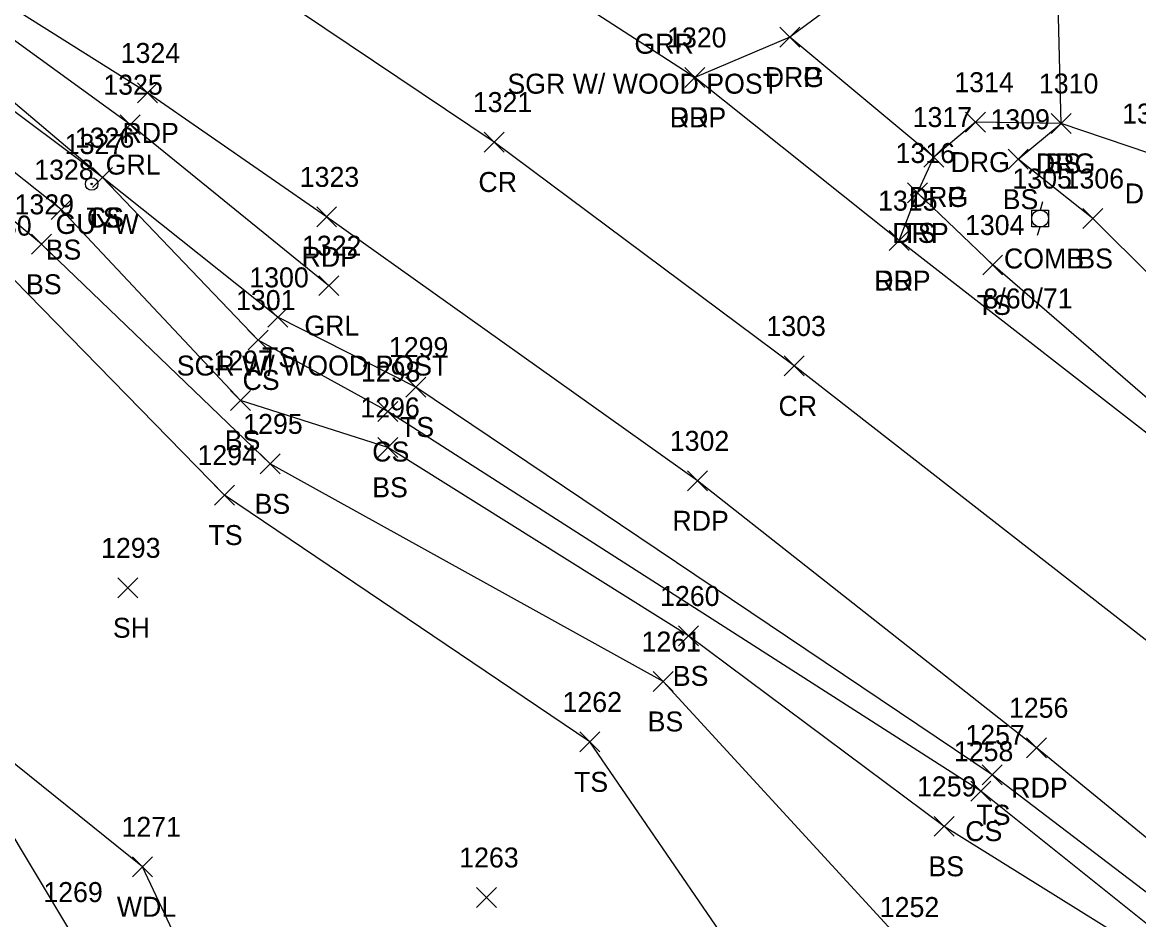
# Model space of a CAD drawing. Extents: x 1537342 to 1542195, y 163002 to 168596.
# Drawn here: x 1541827.1 to 1541938.8, y 163200.7 to 163290.5 of the extents above; entities that cross this region are included whole.
import ezdxf

# ---------------------------------------------------------------- set-up
doc = ezdxf.new("R2010")
doc.units = 0
for name, color, linetype in [('L_A', 7, 'Continuous'), ('L_I', 7, 'Continuous'), ('L_TIC', 7, 'Continuous'), ('LAWA', 7, 'Continuous'), ('LELB', 7, 'Continuous'), ('P_A', 7, 'Continuous'), ('P_I', 7, 'Continuous'), ('P_TIC', 7, 'Continuous'), ('PET', 7, 'Continuous'), ('PRC', 7, 'Continuous'), ('R_A', 7, 'Continuous'), ('R_C', 7, 'Continuous'), ('R_I', 7, 'Continuous'), ('R_TIC', 7, 'Continuous'), ('RDG', 7, 'Continuous'), ('RDP', 7, 'Continuous'), ('RGR', 7, 'Continuous'), ('U_A', 7, 'Continuous'), ('U_C', 7, 'Continuous'), ('U_I', 7, 'Continuous'), ('UP', 7, 'Continuous'), ('UPGW', 7, 'Continuous')]:
    doc.layers.add(name, color=color, linetype=linetype)

msp = doc.modelspace()

# ---------------------------------------------------------------- linework, layer by layer
at = {"layer": 'L_TIC'}
for points in [[(1541930.05, 163279.39), (1541932.05, 163281.39)], [(1541932.05, 163279.39), (1541930.05, 163281.39)], [(1541925.76, 163275.81), (1541927.76, 163277.81)], [(1541927.76, 163275.81), (1541925.76, 163277.81)], [(1541834.08, 163273.97), (1541836.08, 163275.97)], [(1541836.08, 163273.97), (1541834.08, 163275.97)], [(1541834.08, 163273.97), (1541836.08, 163275.97)], [(1541836.08, 163273.97), (1541834.08, 163275.97)], [(1541915.66, 163272.43), (1541917.66, 163274.43)], [(1541917.66, 163272.43), (1541915.66, 163274.43)], [(1541829.96, 163270.76), (1541831.96, 163272.76)], [(1541831.96, 163270.76), (1541829.96, 163272.76)], [(1541933.22, 163269.87), (1541935.22, 163271.87)], [(1541935.22, 163269.87), (1541933.22, 163271.87)], [(1541827.99, 163267.29), (1541829.99, 163269.29)], [(1541829.99, 163267.29), (1541827.99, 163269.29)], [(1541923.2, 163265.22), (1541925.2, 163267.22)], [(1541925.2, 163265.22), (1541923.2, 163267.22)], [(1541851.65, 163259.98), (1541853.65, 163261.98)], [(1541853.65, 163259.98), (1541851.65, 163261.98)], [(1541849.67, 163257.71), (1541851.67, 163259.71)], [(1541851.67, 163257.71), (1541849.67, 163259.71)], [(1541865.46, 163253), (1541867.46, 163255)], [(1541867.46, 163253), (1541865.46, 163255)], [(1541847.89, 163251.66), (1541849.89, 163253.66)], [(1541849.89, 163251.66), (1541847.89, 163253.66)], [(1541862.65, 163250.54), (1541864.65, 163252.54)], [(1541864.65, 163250.54), (1541862.65, 163252.54)], [(1541862.64, 163246.96), (1541864.64, 163248.96)], [(1541864.64, 163246.96), (1541862.64, 163248.96)], [(1541850.87, 163245.31), (1541852.87, 163247.31)], [(1541852.87, 163245.31), (1541850.87, 163247.31)], [(1541846.29, 163242.18), (1541848.29, 163244.18)], [(1541848.29, 163242.18), (1541846.29, 163244.18)], [(1541836.64, 163232.9), (1541838.64, 163234.9)], [(1541838.64, 163232.9), (1541836.64, 163234.9)], [(1541892.74, 163228.08), (1541894.74, 163230.08)], [(1541894.74, 163228.08), (1541892.74, 163230.08)], [(1541890.22, 163223.52), (1541892.22, 163225.52)], [(1541892.22, 163223.52), (1541890.22, 163225.52)], [(1541882.88, 163217.47), (1541884.88, 163219.47)], [(1541884.88, 163217.47), (1541882.88, 163219.47)], [(1541923.16, 163214.18), (1541925.16, 163216.18)], [(1541925.16, 163214.18), (1541923.16, 163216.18)], [(1541922.01, 163212.54), (1541924.01, 163214.54)], [(1541924.01, 163212.54), (1541922.01, 163214.54)], [(1541918.33, 163209.02), (1541920.33, 163211.02)], [(1541920.33, 163209.02), (1541918.33, 163211.02)], [(1541838.11, 163204.97), (1541840.11, 163206.97)], [(1541840.11, 163204.97), (1541838.11, 163206.97)], [(1541872.54, 163201.9), (1541874.54, 163203.9)], [(1541874.54, 163201.9), (1541872.54, 163203.9)]]:
    msp.add_lwpolyline(points, dxfattribs=at)
at = {"layer": 'LAWA'}
msp.add_lwpolyline([(1541844.86, 163168.93), (1541849.55, 163183.81), (1541839.11, 163205.97), (1541817.65, 163223.23), (1541815, 163239.81), (1541816.56, 163255.64), (1541792.4, 163274.28), (1541779.24, 163270.52), (1541762.88, 163259.76), (1541752.39, 163275.43), (1541738.68, 163268.21), (1541722.17, 163262.13), (1541701.08, 163257.12)], dxfattribs=at)
at = {"layer": 'LELB'}
for points in [[(1542002.44, 163218.44), (1541992.58, 163218.5), (1541981.66, 163227.08), (1541972.73, 163235.18), (1541952.24, 163252.94), (1541934.22, 163270.87), (1541926.76, 163276.81), (1541931.05, 163280.39), (1541930.67, 163296.4), (1541914.43, 163302.12), (1541899.5, 163302.03), (1541884.5, 163312), (1541872.6, 163319.6), (1541857.31, 163324.7)], [(1541981.52, 163166.61), (1541978.59, 163174.42), (1541956.98, 163190.15), (1541924.16, 163215.18), (1541866.46, 163254), (1541852.65, 163260.98), (1541835.08, 163274.97), (1541811.52, 163294.95), (1541800.6, 163304.36), (1541792.57, 163308.98)], [(1541955.89, 163187.24), (1541923.01, 163213.54), (1541863.65, 163251.54), (1541850.67, 163258.71), (1541835.08, 163274.97), (1541811.38, 163292.75), (1541797.03, 163303.08), (1541792.37, 163306.6)], [(1541982.35, 163154.54), (1541977.46, 163162.71), (1541976.49, 163171.88), (1541973.52, 163173.98), (1541972.19, 163175.21), (1541955.89, 163187.24), (1541919.33, 163210.02), (1541893.74, 163229.08), (1541863.64, 163247.96), (1541848.89, 163252.66), (1541830.96, 163271.76), (1541807.53, 163290.35), (1541793.3, 163299.34), (1541792.63, 163303.62)], [(1541920.52, 163124.04), (1541935.16, 163148.54), (1541933.92, 163173.02), (1541915.6, 163197.94), (1541891.22, 163224.52), (1541851.87, 163246.31), (1541828.99, 163268.29), (1541806.16, 163287.41), (1541789.02, 163298.58), (1541787.18, 163300.8)], [(1541912.53, 163131.42), (1541929, 163149.96), (1541922.93, 163163.15), (1541906.57, 163185.36), (1541883.88, 163218.47), (1541847.29, 163243.18), (1541824.83, 163266.16), (1541803.8, 163284.14), (1541786.25, 163296.89)], [(1541999.83, 163204.61), (1541992.06, 163211.09), (1541976.95, 163222.64), (1541968.56, 163229.41), (1541948.76, 163245.02), (1541924.2, 163266.22), (1541916.66, 163273.43)], [(1541844.86, 163168.93), (1541831.91, 163199.44), (1541817.65, 163223.23), (1541791.64, 163233.2), (1541773.3, 163225.27), (1541742.38, 163225.52), (1541715.33, 163231.42)]]:
    msp.add_lwpolyline(points, dxfattribs=at)
at = {"layer": 'P_TIC'}
for points in [[(1541893.39, 163284), (1541895.39, 163286)], [(1541895.39, 163284), (1541893.39, 163286)], [(1541838.6, 163282.45), (1541840.6, 163284.45)], [(1541840.6, 163282.45), (1541838.6, 163284.45)], [(1541873.29, 163277.53), (1541875.29, 163279.53)], [(1541875.29, 163277.53), (1541873.29, 163279.53)], [(1541856.53, 163270.04), (1541858.53, 163272.04)], [(1541858.53, 163270.04), (1541856.53, 163272.04)], [(1541913.85, 163267.66), (1541915.85, 163269.66)], [(1541915.85, 163267.66), (1541913.85, 163269.66)], [(1541903.32, 163255.11), (1541905.32, 163257.11)], [(1541905.32, 163255.11), (1541903.32, 163257.11)], [(1541893.65, 163243.61), (1541895.65, 163245.61)], [(1541895.65, 163243.61), (1541893.65, 163245.61)], [(1541927.58, 163216.89), (1541929.58, 163218.89)], [(1541929.58, 163216.89), (1541927.58, 163218.89)]]:
    msp.add_lwpolyline(points, dxfattribs=at)
at = {"layer": 'PET'}
for points in [[(1542165.56, 163030.05), (1542126.67, 163058.36), (1542096.32, 163082.47), (1542058.61, 163112.54), (1542052.02, 163117.84), (1542010.73, 163151.35), (1541978.73, 163177.48), (1541958.58, 163193.33), (1541928.58, 163217.89), (1541894.65, 163244.61), (1541857.53, 163271.04), (1541839.6, 163283.45), (1541795.58, 163311.16), (1541814.19, 163318.82), (1541832.22, 163326.69)], [(1542182.46, 163052.97), (1542144.74, 163083.14), (1542111.59, 163110.07), (1542069.86, 163143.45), (1542042.93, 163166.04), (1542014.58, 163189.13), (1541996.52, 163203.32), (1541975.27, 163220.84), (1541953.96, 163238.23), (1541914.85, 163268.66), (1541894.39, 163285), (1541874.19, 163298.08), (1541854.83, 163311.47), (1541832.22, 163326.69)]]:
    msp.add_lwpolyline(points, dxfattribs=at)
at = {"layer": 'PRC'}
msp.add_lwpolyline([(1542174.18, 163041.84), (1542135.38, 163070.51), (1542102.15, 163097.42), (1542058.02, 163132.98), (1542032.76, 163153.88), (1541982.81, 163194.28), (1541947.35, 163222.57), (1541904.32, 163256.11), (1541874.29, 163278.53), (1541825.99, 163311), (1541814.19, 163318.82)], dxfattribs=at)
at = {"layer": 'R_TIC'}
for points in [[(1541902.89, 163288.03), (1541904.89, 163290.03)], [(1541904.89, 163288.03), (1541902.89, 163290.03)], [(1541902.89, 163288.03), (1541904.89, 163290.03)], [(1541904.89, 163288.03), (1541902.89, 163290.03)], [(1541893.39, 163284), (1541895.39, 163286)], [(1541895.39, 163284), (1541893.39, 163286)], [(1541836.87, 163279.27), (1541838.87, 163281.27)], [(1541838.87, 163279.27), (1541836.87, 163281.27)], [(1541921.49, 163279.52), (1541923.49, 163281.52)], [(1541923.49, 163279.52), (1541921.49, 163281.52)], [(1541930.05, 163279.39), (1541932.05, 163281.39)], [(1541932.05, 163279.39), (1541930.05, 163281.39)], [(1541917.32, 163276.03), (1541919.32, 163278.03)], [(1541919.32, 163276.03), (1541917.32, 163278.03)], [(1541917.32, 163276.03), (1541919.32, 163278.03)], [(1541919.32, 163276.03), (1541917.32, 163278.03)], [(1541915.66, 163272.43), (1541917.66, 163274.43)], [(1541917.66, 163272.43), (1541915.66, 163274.43)], [(1541913.85, 163267.66), (1541915.85, 163269.66)], [(1541915.85, 163267.66), (1541913.85, 163269.66)], [(1541856.75, 163263.15), (1541858.75, 163265.15)], [(1541858.75, 163263.15), (1541856.75, 163265.15)]]:
    msp.add_lwpolyline(points, dxfattribs=at)
at = {"layer": 'RDG'}
for points in [[(1542017.62, 163206.92), (1542015.2, 163226.11), (1542009.88, 163243.69), (1541994.5, 163258.92), (1541988.52, 163265.14), (1541982.39, 163272.12), (1541977.91, 163278.25), (1541973.34, 163281.58), (1541963.15, 163285.49), (1541948.66, 163292.51), (1541930.67, 163296.4), (1541918.38, 163296.03), (1541913.61, 163296.24), (1541903.89, 163289.03)], [(1542002.85, 163214.55), (1542002.44, 163218.44), (1541997.04, 163236.79), (1541985.19, 163249.9), (1541958.7, 163267.58), (1541939.93, 163277.38), (1541931.05, 163280.39), (1541922.49, 163280.52), (1541918.32, 163277.03)]]:
    msp.add_lwpolyline(points, dxfattribs=at)
at = {"layer": 'RDP'}
msp.add_lwpolyline([(1541914.85, 163268.66), (1541916.66, 163273.43), (1541918.32, 163277.03), (1541903.89, 163289.03), (1541894.39, 163285)], dxfattribs=at)
at = {"layer": 'RGR'}
msp.add_lwpolyline([(1541857.75, 163264.15), (1541837.87, 163280.27), (1541804.45, 163304.56), (1541795.02, 163310.6)], dxfattribs=at)
at = {"layer": 'UP'}
for p, q in [((1541928.11, 163270.04), (1541928.11, 163271.7)), ((1541928.11, 163271.7), (1541929.78, 163271.7)), ((1541929.2, 163272.54), (1541928.95, 163271.7)), ((1541929.78, 163271.7), (1541929.78, 163270.04)), ((1541928.95, 163270.87), (1541928.95, 163270.87)), ((1541929.78, 163270.04), (1541928.11, 163270.04)), ((1541928.7, 163269.2), (1541928.95, 163270.04))]:
    msp.add_line(p, q, dxfattribs=at)
msp.add_circle((1541928.95, 163270.87), 0.833, dxfattribs=at)
at = {"layer": 'UPGW'}
for radius in [0.625, 0.0833]:
    msp.add_circle((1541834.01, 163274.33), radius, dxfattribs=at)

# ---------------------------------------------------------------- texts
at = {"layer": 'L_A'}
for s, p in [('BS', (1541929.49, 163275.39)), ('BS', (1541925.2, 163271.81)), ('TS', (1541833.49, 163269.97)), ('CS', (1541833.52, 163269.97)), ('TS', (1541915.07, 163268.43)), ('BS', (1541829.4, 163266.76)), ('BS', (1541932.67, 163265.87)), ('BS', (1541827.43, 163263.29)), ('TS', (1541922.61, 163261.22)), ('TS', (1541851.05, 163255.98)), ('CS', (1541849.11, 163253.71)), ('TS', (1541864.87, 163249)), ('BS', (1541847.33, 163247.66)), ('CS', (1541862.09, 163246.54)), ('BS', (1541862.09, 163242.96)), ('BS', (1541850.31, 163241.31)), ('TS', (1541845.7, 163238.18)), ('SH', (1541836.13, 163228.9)), ('BS', (1541892.18, 163224.08)), ('BS', (1541889.66, 163219.52)), ('TS', (1541882.29, 163213.47)), ('TS', (1541922.57, 163210.18)), ('CS', (1541921.45, 163208.54)), ('BS', (1541917.77, 163205.02)), ('WDL', (1541836.53, 163200.97))]:
    msp.add_text(s, height=2, dxfattribs=at).set_placement(p)
at = {"layer": 'L_I'}
for s, p in [('1310', (1541928.83, 163283.39)), ('1309', (1541923.98, 163279.81)), ('1326', (1541832.33, 163277.97)), ('1326', (1541832.33, 163277.97)), ('1316', (1541914.48, 163276.43)), ('1328', (1541828.26, 163274.76)), ('1306', (1541931.4, 163273.87)), ('1329', (1541826.29, 163271.29)), ('1330', (1541822.05, 163269.16)), ('1304', (1541921.43, 163269.22)), ('1300', (1541849.79, 163263.98)), ('1301', (1541848.46, 163261.71)), ('1299', (1541863.76, 163257)), ('1297', (1541846.2, 163255.66)), ('1298', (1541860.96, 163254.54)), ('1296', (1541860.9, 163250.96)), ('1295', (1541849.18, 163249.31)), ('1294', (1541844.6, 163246.18)), ('1293', (1541834.95, 163236.9)), ('1260', (1541890.91, 163232.08)), ('1261', (1541889.05, 163227.52)), ('1262', (1541881.14, 163221.47)), ('1257', (1541921.47, 163218.18)), ('1258', (1541920.32, 163216.54)), ('1259', (1541916.63, 163213.02)), ('1271', (1541836.99, 163208.97)), ('1263', (1541870.8, 163205.9)), ('1269', (1541829.17, 163202.44)), ('1252', (1541912.9, 163200.94))]:
    msp.add_text(s, height=2, dxfattribs=at).set_placement(p)
at = {"layer": 'P_A'}
for s, p in [('RDP', (1541891.88, 163280)), ('RDP', (1541837.09, 163278.45)), ('CR', (1541872.72, 163273.53)), ('RDP', (1541855.02, 163266.04)), ('RDP', (1541912.34, 163263.66)), ('CR', (1541902.76, 163251.11)), ('RDP', (1541892.14, 163239.61)), ('RDP', (1541926.06, 163212.89))]:
    msp.add_text(s, height=2, dxfattribs=at).set_placement(p)
at = {"layer": 'P_I'}
for s, p in [('1320', (1541891.61, 163288)), ('1324', (1541836.91, 163286.45)), ('1321', (1541872.16, 163281.53)), ('1323', (1541854.84, 163274.04)), ('1315', (1541912.73, 163271.66)), ('1303', (1541901.55, 163259.11)), ('1302', (1541891.88, 163247.61)), ('1256', (1541925.83, 163220.89))]:
    msp.add_text(s, height=2, dxfattribs=at).set_placement(p)
at = {"layer": 'R_A'}
for s, p in [('GRR', (1541888.34, 163287.37)), ('DRG', (1541901.38, 163284.03)), ('DRP', (1541901.38, 163284.03)), ('DRP', (1541891.88, 163280)), ('GRL', (1541835.41, 163275.27)), ('DRG', (1541919.98, 163275.52)), ('DRG', (1541928.53, 163275.39)), ('DRG', (1541915.81, 163272.03)), ('DRP', (1541915.81, 163272.03)), ('DRG', (1541937.42, 163272.38)), ('DRP', (1541914.15, 163268.43)), ('DRP', (1541912.34, 163263.66)), ('GRL', (1541855.3, 163259.15))]:
    msp.add_text(s, height=2, dxfattribs=at).set_placement(p)
at = {"layer": 'R_C'}
for p in [(1541875.62, 163283.37), (1541842.52, 163255.15)]:
    msp.add_text('SGR W/ WOOD POST', height=2, dxfattribs=at).set_placement(p)
at = {"layer": 'R_I'}
for s, p in [('1320', (1541891.61, 163288)), ('1325', (1541835.17, 163283.27)), ('1314', (1541920.36, 163283.52)), ('1310', (1541928.83, 163283.39)), ('1317', (1541916.19, 163280.03)), ('1317', (1541916.19, 163280.03)), ('1307', (1541937.16, 163280.38)), ('1316', (1541914.48, 163276.43)), ('1315', (1541912.73, 163271.66)), ('1322', (1541855.06, 163267.15))]:
    msp.add_text(s, height=2, dxfattribs=at).set_placement(p)
at = {"layer": 'U_A'}
for s, p in [('GUYW', (1541830.4, 163269.33)), ('COMB', (1541925.33, 163265.87))]:
    msp.add_text(s, height=2, dxfattribs=at).set_placement(p)
at = {"layer": 'U_C'}
msp.add_text('8/60/71', height=2, dxfattribs=at).set_placement((1541923.28, 163261.87))
at = {"layer": 'U_I'}
for s, p in [('1327', (1541831.31, 163277.33)), ('1305', (1541926.18, 163273.87))]:
    msp.add_text(s, height=2, dxfattribs=at).set_placement(p)

doc.saveas('drawing.dxf')
